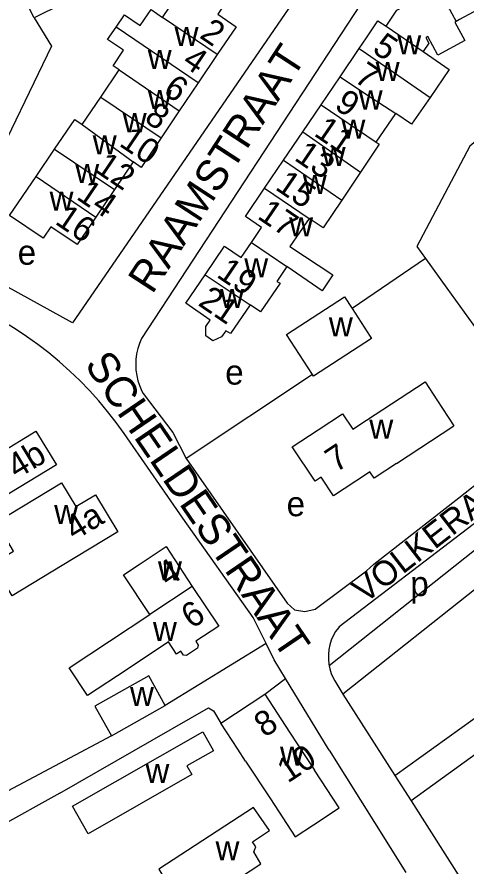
# Model space of a CAD drawing. Extents: x 156721 to 158827, y 386657 to 388950.
# Drawn here: x 157643.5 to 157716.1, y 387463.7 to 387600.8 of the extents above; entities that cross this region are included whole.
import ezdxf

# ---------------------------------------------------------------- set-up
doc = ezdxf.new("R2010")
doc.units = 0
for name, color, linetype in [('BLT_Basislijn', 7, 'Continuous'), ('BLT_Bebouwing', 7, 'Continuous'), ('BLT_Centroide', 7, 'Continuous'), ('BLT_Huisnummer', 7, 'Continuous'), ('BLT_Huisnummer_ tussenligend', 7, 'Continuous'), ('BLT_Huisnummer_reeks', 7, 'Continuous'), ('BLT_Onderverdeling_panden', 7, 'Continuous'), ('BLT_Straatnaam', 7, 'Continuous'), ('BLT_Straatnaam_verkleind', 7, 'Continuous')]:
    doc.layers.add(name, color=color, linetype=linetype)

msp = doc.modelspace()

# ---------------------------------------------------------------- linework, layer by layer
at = {"layer": 'BLT_Basislijn'}
for p, q in [((157709.51, 387561.84), (157697.66, 387553.74)), ((157709.51, 387561.84), (157712.96, 387557.04)), ((157712.96, 387557.04), (157722.95, 387543.14)), ((157691.26, 387543.06), (157670.85, 387529.49)), ((157669.33, 387521.3), (157660.86, 387533.53)), ((157729.65, 387528.34), (157695.6, 387502.34)), ((157714.91, 387523.14), (157721.26, 387528.21)), ((157729.65, 387524.37), (157693.96, 387496.05)), ((157729.65, 387517.99), (157696.18, 387491.43)), ((157704.59, 387478.29), (157748.48, 387510)), ((157750.77, 387505.81), (157707.19, 387474.21)), ((157683.79, 387499.61), (157667.48, 387489.62)), ((157683.56, 387491.43), (157686.93, 387493.98)), ((157693.95, 387482.42), (157686.93, 387493.98)), ((157694.87, 387493.59), (157696.18, 387491.43)), ((157696.18, 387491.43), (157704.59, 387478.29)), ((157658.77, 387484.73), (157632.16, 387470.6)), ((157693.95, 387482.42), (157706.33, 387462.63)), ((157704.59, 387478.29), (157707.19, 387474.21)), ((157650.46, 387475.48), (157635.17, 387467.02)), ((157707.19, 387474.21), (157729.65, 387439.08))]:
    msp.add_line(p, q, dxfattribs=at)
for points in [[(157715.3, 387610.4), (157712.01, 387616.64), (157710.73, 387616.48), (157706.1, 387613), (157700, 387604.4), (157663.66, 387548.92)], [(157688.52, 387603.84), (157652.49, 387551.43), (157640.05, 387558.25)], [(157646.27, 387600.68), (157649.08, 387596.1), (157638.99, 387575.21)], [(157721, 387583.59), (157716.71, 387579.95), (157708.13, 387563.76), (157709.51, 387561.84)], [(157660.86, 387533.53), (157659.55, 387535.34), (157658.17, 387537.1), (157656.73, 387538.82), (157655.23, 387540.48), (157653.67, 387542.09), (157652.06, 387543.64), (157650.39, 387545.13), (157648.67, 387546.56), (157646.9, 387547.93), (157645.08, 387549.23), (157643.21, 387550.47), (157641.31, 387551.64), (157639.36, 387552.74), (157637.37, 387553.78), (157635.35, 387554.74), (157633.3, 387555.62), (157632.59, 387555.91)], [(157663.66, 387548.92), (157663.31, 387548.11), (157663.04, 387547.27), (157662.85, 387546.41), (157662.73, 387545.53), (157662.7, 387544.65), (157662.74, 387543.77), (157662.87, 387542.9), (157663.07, 387542.04), (157663.35, 387541.2), (157663.7, 387540.4), (157663.91, 387540)], [(157663.91, 387540), (157668.68, 387533.69), (157670.85, 387529.49)], [(157670.85, 387529.49), (157687.16, 387506.15), (157688.34, 387505.07), (157690.03, 387504.8), (157691.69, 387505.16), (157700, 387511.37), (157701.17, 387512.45), (157714.91, 387523.14)], [(157683.79, 387499.61), (157681.68, 387503.84), (157670.34, 387519.85), (157669.33, 387521.3)], [(157695.6, 387502.34), (157695.46, 387502.18), (157695.01, 387501.55), (157694.63, 387500.87), (157694.31, 387500.16), (157694.07, 387499.41), (157693.91, 387498.65), (157693.83, 387497.87), (157693.83, 387497.09), (157693.91, 387496.32), (157693.96, 387496.05)], [(157686.93, 387493.98), (157685.09, 387497), (157683.79, 387499.61)], [(157693.96, 387496.05), (157694.06, 387495.55), (157694.3, 387494.81), (157694.61, 387494.09), (157694.87, 387493.59)], [(157650.46, 387475.48), (157674.49, 387489.24), (157675.27, 387488.78), (157676.44, 387486.75)]]:
    msp.add_lwpolyline(points, dxfattribs=at)
at = {"layer": 'BLT_Bebouwing'}
for p, q in [((157646.27, 387600.68), (157635.77, 387621.87)), ((157695.74, 387591.18), (157698.82, 387595.74)), ((157675.89, 387594.74), (157672.82, 387590.21)), ((157657.04, 387587.87), (157660.03, 387592.29)), ((157672.82, 387590.21), (157669.75, 387585.68)), ((157692.65, 387586.63), (157695.74, 387591.18)), ((157689.69, 387582.27), (157692.65, 387586.63)), ((157669.75, 387585.68), (157666.79, 387581.3)), ((157686.6, 387577.72), (157689.69, 387582.27)), ((157646.59, 387575.05), (157649.6, 387579.5)), ((157683.51, 387573.17), (157686.6, 387577.72)), ((157662.28, 387577.41), (157659.27, 387572.96)), ((157699, 387575.74), (157696, 387571.26)), ((157659.27, 387572.96), (157656.25, 387568.51)), ((157690.71, 387568.29), (157687.62, 387563.73)), ((157681.41, 387564.41), (157683.05, 387566.84)), ((157679.76, 387561.98), (157681.41, 387564.41)), ((157696.43, 387555.62), (157697.66, 387553.74)), ((157697.66, 387553.74), (157700.58, 387549.23)), ((157704.82, 387528.7), (157714.12, 387534.81)), ((157676.44, 387486.75), (157683.56, 387491.43)), ((157683.56, 387491.43), (157687.57, 387485.31)), ((157658.77, 387484.73), (157667.48, 387489.62)), ((157687.57, 387485.31), (157691.59, 387479.2)), ((157680.45, 387480.64), (157684.47, 387474.53)), ((157655.01, 387468.91), (157652.49, 387473.36))]:
    msp.add_line(p, q, dxfattribs=at)
for points in [[(157667.03, 387600.74), (157674.31, 387611.49), (157680.2, 387607.51), (157675.98, 387601.28), (157678.95, 387599.26), (157675.89, 387594.74)], [(157703.16, 387599.33), (157704.92, 387601.9), (157706.64, 387602.83), (157705.43, 387605.06), (157710.36, 387607.73)], [(157651.26, 387606.47), (157650.3, 387605.99), (157651.62, 387603.33), (157650.75, 387602.9), (157646.27, 387600.68)], [(157719.42, 387602.79), (157715.02, 387600.41), (157714.48, 387600.12)], [(157659.54, 387599.2), (157660.87, 387601.17), (157663.43, 387599.43), (157665.19, 387602.02), (157667.03, 387600.74)], [(157698.82, 387595.74), (157700, 387597.47), (157701.84, 387600.18), (157703.16, 387599.33)], [(157714.48, 387600.12), (157714.25, 387600), (157715.86, 387597.02), (157711.53, 387594.68), (157709.92, 387597.66), (157709.61, 387597.49), (157710.08, 387596.61), (157709.14, 387595.23)], [(157660.03, 387592.29), (157659.05, 387592.96), (157660.74, 387595.44), (157658.17, 387597.18), (157659.54, 387599.2)], [(157709.14, 387595.23), (157713.36, 387592.36), (157710.3, 387587.82)], [(157654.06, 387583.47), (157657.04, 387587.87)], [(157710.3, 387587.82), (157707.27, 387583.5), (157704.73, 387585.22)], [(157701.55, 387580.58), (157704.73, 387585.22)], [(157649.6, 387579.5), (157652.84, 387584.29), (157654.06, 387583.47)], [(157666.79, 387581.3), (157663.56, 387576.54), (157662.28, 387577.41)], [(157701.55, 387580.58), (157702.02, 387580.26), (157699, 387575.74)], [(157656.25, 387568.51), (157653.24, 387564.06), (157648.99, 387566.93), (157647.75, 387565.1), (157642.33, 387568.76), (157646.59, 387575.05)], [(157683.05, 387566.84), (157680.42, 387568.62), (157683.51, 387573.17)], [(157696, 387571.26), (157693.01, 387566.79), (157690.71, 387568.29)], [(157673.91, 387559.2), (157677.05, 387563.82), (157679.76, 387561.98)], [(157687.62, 387563.73), (157694.58, 387559.19), (157692.84, 387556.62), (157687.14, 387560.52)], [(157687.14, 387560.52), (157685.49, 387558.09)], [(157681.18, 387554.34), (157678.01, 387549.68), (157677.29, 387550.16), (157676.59, 387549.14), (157675.19, 387548.51), (157674.02, 387549.3), (157674.06, 387550.86), (157674.76, 387551.88), (157670.78, 387554.58), (157673.91, 387559.2)], [(157685.49, 387558.09), (157686.03, 387557.82), (157682.89, 387553.18), (157681.18, 387554.34)], [(157691.26, 387543.06), (157687.06, 387549.55), (157696.43, 387555.62)], [(157700.58, 387549.23), (157700.79, 387548.91), (157691.41, 387542.83), (157691.26, 387543.06)], [(157704.82, 387528.7), (157701.21, 387526.33), (157700.54, 387527.35), (157700, 387526.99), (157694.64, 387523.47), (157692.66, 387526.48), (157691.71, 387525.85), (157688.01, 387531.39), (157692.18, 387534.14), (157696.12, 387536.74), (157697.8, 387534.26), (157700, 387535.71), (157709.45, 387541.92), (157711.37, 387538.99), (157714.12, 387534.81)], [(157646.58, 387533.95), (157649.9, 387528.49), (157640.88, 387523.01), (157638.8, 387526.43), (157635.98, 387524.72), (157635.46, 387525.58), (157633.11, 387524.16), (157633.89, 387522.87), (157629.36, 387520.12), (157628.58, 387521.41), (157625.42, 387519.49), (157622.88, 387523.68), (157632.92, 387529.77), (157638.7, 387533.28), (157640.52, 387530.28), (157646.58, 387533.95)], [(157656.19, 387523.65), (157659.82, 387517.66), (157650.82, 387512.22), (157642.75, 387507.32), (157639.6, 387512.53), (157642.95, 387514.55), (157640.14, 387519.21), (157650.69, 387525.61), (157653.04, 387521.74), (157656.19, 387523.65)], [(157665, 387504.32), (157660.75, 387510.74), (157663.43, 387512.52), (157667.6, 387515.28), (157671.85, 387508.85)], [(157671.85, 387508.85), (157676.11, 387502.43), (157672.44, 387500), (157672.79, 387499.34), (157672.68, 387498.89), (157670.9, 387497.71), (157670.41, 387497.77), (157670.01, 387498.39), (157669.31, 387497.93), (157668.01, 387499.89), (157661.31, 387495.46)], [(157661.31, 387495.46), (157654.91, 387491.22), (157651.93, 387495.72), (157665, 387504.32)], [(157667.48, 387489.62), (157664.8, 387494.4), (157656.09, 387489.51), (157658.77, 387484.73)], [(157680.45, 387480.64), (157679.18, 387482.57), (157676.44, 387486.75)], [(157652.49, 387473.36), (157673.55, 387485.34), (157675.27, 387482.32), (157670.98, 387479.88), (157671.79, 387478.45), (157655.01, 387468.91)], [(157684.47, 387474.53), (157688.48, 387468.42), (157691.42, 387470.35), (157695.6, 387473.09), (157691.59, 387479.2)], [(157666.44, 387463.2), (157670.68, 387456.05), (157682.93, 387464.05), (157681.77, 387465.99), (157682.11, 387466.77), (157681.57, 387467.6), (157684.32, 387469.44), (157681.74, 387473.17), (157666.44, 387463.2)]]:
    msp.add_lwpolyline(points, dxfattribs=at)
at = {"layer": 'BLT_Onderverdeling_panden'}
for p, q in [((157710.36, 387607.73), (157714.48, 387600.12)), ((157675.89, 387594.74), (157667.03, 387600.74)), ((157672.82, 387590.21), (157659.54, 387599.2)), ((157703.16, 387599.33), (157709.14, 387595.23)), ((157660.03, 387592.29), (157669.75, 387585.68)), ((157657.04, 387587.87), (157666.79, 387581.3)), ((157692.65, 387586.63), (157701.55, 387580.58)), ((157654.06, 387583.47), (157662.28, 387577.41)), ((157689.69, 387582.27), (157699, 387575.74)), ((157649.6, 387579.5), (157659.27, 387572.96)), ((157686.6, 387577.72), (157696, 387571.26)), ((157646.59, 387575.05), (157656.25, 387568.51)), ((157683.51, 387573.17), (157690.71, 387568.29)), ((157681.41, 387564.41), (157687.14, 387560.52)), ((157673.91, 387559.2), (157681.18, 387554.34)), ((157671.85, 387508.85), (157665, 387504.32))]:
    msp.add_line(p, q, dxfattribs=at)
for points in [[(157698.82, 387595.74), (157700, 387594.94), (157710.3, 387587.82)], [(157695.74, 387591.18), (157700, 387588.31), (157704.73, 387585.22)]]:
    msp.add_lwpolyline(points, dxfattribs=at)

# ---------------------------------------------------------------- texts
at = {"layer": 'BLT_Centroide'}
for s, p in [('w', (157668.98, 387596.12)), ('w', (157704.98, 387594.81)), ('w', (157664.65, 387592.44)), ('w', (157701.48, 387590.47)), ('w', (157664.65, 387585.94)), ('w', (157698.73, 387585.88)), ('w', (157660.6, 387582.22)), ('w', (157695.95, 387581.19)), ('w', (157655.76, 387578.62)), ('w', (157692.76, 387576.78)), ('w', (157652.93, 387574)), ('w', (157689.71, 387572.25)), ('w', (157648.78, 387569.56)), ('w', (157687.5, 387565.38)), ('e', (157643.63, 387560.81)), ('w', (157680.24, 387558.78)), ('w', (157676.34, 387553.84)), ('w', (157693.92, 387549.22)), ('e', (157677.17, 387541.45)), ('w', (157700.45, 387532.69)), ('e', (157687.09, 387520.19)), ('w', (157649.53, 387518.91)), ('w', (157666.3, 387509.81)), ('p', (157707.07, 387507.29)), ('w', (157665.49, 387500.03)), ('w', (157661.78, 387489.56)), ('w', (157686.02, 387479.92)), ('w', (157664.28, 387477.12)), ('w', (157675.6, 387464.62))]:
    msp.add_text(s, height=4, dxfattribs=at).set_placement(p)
at = {"layer": 'BLT_Huisnummer'}
for s, rotation, p in [('2', 325.8971, (157672.85, 387597.58)), ('5', 325.6608, (157700.76, 387595.25)), ('6', 325.8971, (157666.91, 387588.52)), ('9', 325.8391, (157694.62, 387586.13)), ('10', 325.8971, (157659.86, 387580.13)), ('13', 325.8444, (157688.15, 387577.82)), ('17', 325.8249, (157682.19, 387568.38)), ('16', 325.8971, (157649.49, 387567.52)), ('21', 325.8335, (157672.61, 387554.36)), ('4b', 31.2561, (157643.48, 387526.12)), ('7', 33.3158, (157695.03, 387527.16)), ('4a', 31.1955, (157652.79, 387516.15)), ('4', 33.5083, (157667.93, 387508.67)), ('6', 33.5131, (157671.76, 387501.9))]:
    msp.add_text(s, height=4, rotation=rotation, dxfattribs=at).set_placement(p)
at = {"layer": 'BLT_Huisnummer_ tussenligend'}
for s, rotation, p in [('4', 325.8971, (157670.02, 387593.11)), ('7', 325.6608, (157697.8, 387590.55)), ('8', 325.8971, (157663.91, 387584.05)), ('11', 325.6608, (157691.33, 387581.77)), ('12', 325.8971, (157655.88, 387575.99)), ('15', 325.6608, (157685.07, 387573.08)), ('14', 325.8971, (157652.93, 387571.53)), ('19', 325.8485, (157675.59, 387558.94))]:
    msp.add_text(s, height=4, rotation=rotation, dxfattribs=at).set_placement(p)
at = {"layer": 'BLT_Huisnummer_reeks'}
for s, rotation, p in [('8', 33.2963, (157683.53, 387484.36)), ('10', 33.306, (157687.27, 387477))]:
    msp.add_text(s, height=4, rotation=rotation, dxfattribs=at).set_placement(p)
at = {"layer": 'BLT_Straatnaam'}
for s, rotation, p in [('RAAMSTRAAT', 56.8917, (157665.37, 387555.9)), ('SCHELDESTRAAT', 304.2986, (157654.32, 387544.66))]:
    msp.add_text(s, height=5, rotation=rotation, dxfattribs=at).set_placement(p)
at = {"layer": 'BLT_Straatnaam_verkleind'}
msp.add_text('VOLKERAK', height=4, rotation=37.7354, dxfattribs=at).set_placement((157699.73, 387506))

doc.saveas('drawing.dxf')
